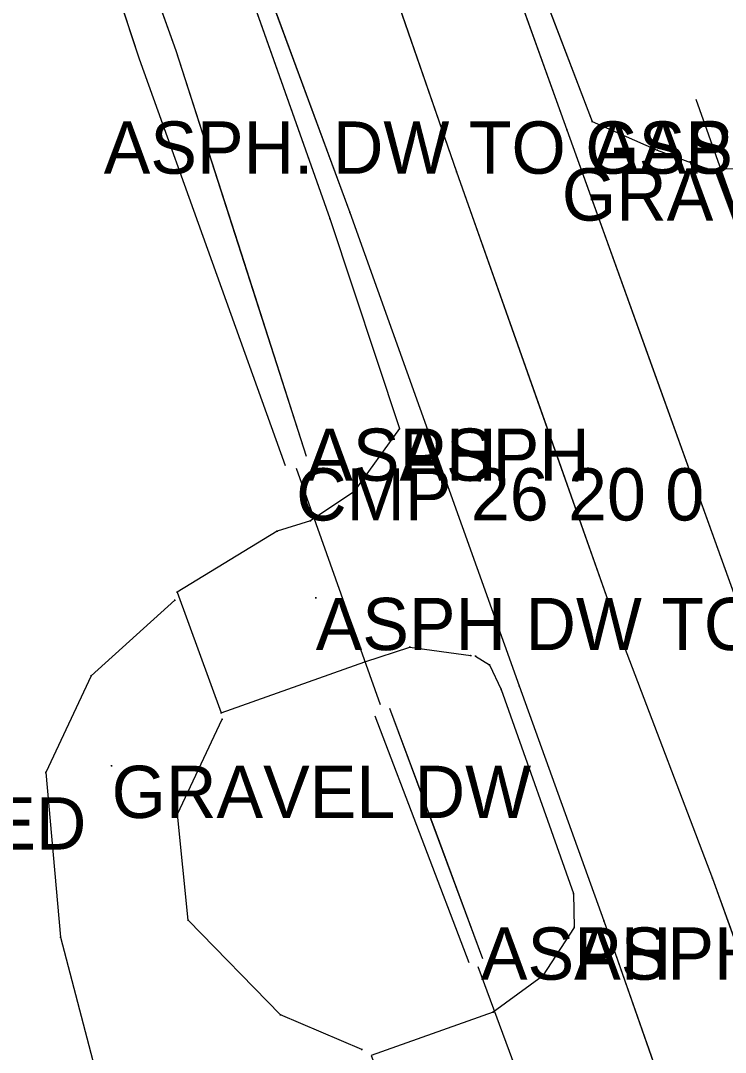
# Model space of a CAD drawing. Extents: x 1050807 to 1053552, y 395828 to 398415.
# Drawn here: x 1052568.2 to 1052635.6, y 396242.6 to 396341.3 of the extents above; entities that cross this region are included whole.
import ezdxf

# ---------------------------------------------------------------- set-up
doc = ezdxf.new("R2010")
doc.units = 0
for name, color, linetype in [('S_BUILDING_ANNOT', 7, 'Continuous'), ('S_DITCHLINE', 7, 'Continuous'), ('S_DRIVEWAY', 7, 'Continuous'), ('S_DRIVEWAY_ANNOT', 7, 'Continuous'), ('S_EDGE_PAVEMENT', 7, 'Continuous'), ('S_MSC_PT_SYM', 7, 'Continuous'), ('S_PAVEMENT_CROWN', 7, 'Continuous'), ('S_RDW_PT_SYM', 7, 'Continuous'), ('S_SHOULDER', 7, 'Continuous'), ('S_SHOULDER_ANNOT', 7, 'Continuous'), ('S_SIDE_DRAIN', 7, 'Continuous'), ('S_SIDE_DRAIN_ANNOT', 7, 'Continuous'), ('S_SURVEY_TEXT_ANNOT', 7, 'Continuous')]:
    doc.layers.add(name, color=color, linetype=linetype)

msp = doc.modelspace()

# ---------------------------------------------------------------- linework, layer by layer
at = {"layer": 'S_DITCHLINE'}
for p, q in [((1052563.191, 396393.977), (1052583.044, 396338.478)), ((1052561.346, 396392.877), (1052579.55, 396337.672)), ((1052583.044, 396338.478), (1052595.516, 396299.665)), ((1052579.55, 396337.672), (1052593.507, 396298.756)), ((1052602.092, 396274.814), (1052611.058, 396251.226)), ((1052603.491, 396275.547), (1052612.378, 396251.614))]:
    msp.add_line(p, q, dxfattribs=at)
for points in [[(1052541.957, 396445.771), (1052547.266, 396432.822), (1052552.574, 396419.874), (1052557.883, 396406.925), (1052563.191, 396393.977), (1052568.155, 396380.102), (1052573.118, 396366.227), (1052578.081, 396352.353), (1052583.044, 396338.478), (1052589.28, 396319.072), (1052595.516, 396299.665)], [(1052536.891, 396443.566), (1052543.005, 396430.894), (1052549.118, 396418.221), (1052555.232, 396405.549), (1052561.346, 396392.877), (1052565.897, 396379.076), (1052570.448, 396365.274), (1052574.999, 396351.473), (1052579.55, 396337.672), (1052586.528, 396318.214), (1052593.507, 396298.756)], [(1052602.092, 396274.814), (1052606.575, 396263.02), (1052611.058, 396251.226)], [(1052603.491, 396275.547), (1052607.934, 396263.58), (1052612.378, 396251.614)]]:
    msp.add_lwpolyline(points, dxfattribs=at)
at = {"layer": 'S_DRIVEWAY'}
for p, q in [((1052622.857, 396331.689), (1052629.097, 396328.944)), ((1052629.097, 396328.944), (1052633.836, 396327.174)), ((1052633.806, 396327.202), (1052655.11, 396326.952)), ((1052604.434, 396302.307), (1052600.061, 396296.258)), ((1052600.061, 396296.258), (1052595.917, 396293.493)), ((1052595.917, 396293.493), (1052592.732, 396292.491)), ((1052592.732, 396292.491), (1052583.161, 396286.642)), ((1052583.161, 396286.642), (1052587.388, 396275.096)), ((1052582.946, 396285.876), (1052574.934, 396278.66)), ((1052601.14, 396279.974), (1052605.445, 396281.406)), ((1052605.445, 396281.406), (1052611.279, 396280.587)), ((1052587.388, 396275.096), (1052601.14, 396279.974)), ((1052574.934, 396278.66), (1052570.597, 396269.388)), ((1052583.197, 396265.401), (1052587.487, 396274.5)), ((1052570.597, 396269.388), (1052572.024, 396253.632)), ((1052584.211, 396255.259), (1052583.197, 396265.401)), ((1052593.051, 396246.228), (1052584.211, 396255.259)), ((1052621.144, 396254.577), (1052618.117, 396249.902)), ((1052572.024, 396253.632), (1052575.274, 396241.216)), ((1052618.117, 396249.902), (1052613.385, 396246.473)), ((1052600.824, 396242.901), (1052593.051, 396246.228)), ((1052613.385, 396246.473), (1052601.718, 396242.339))]:
    msp.add_line(p, q, dxfattribs=at)
for points in [[(1052633.806, 396327.202), (1052655.11, 396326.952), (1052672.463, 396328.566), (1052689.815, 396330.179), (1052703.095, 396334.339), (1052716.376, 396338.498)], [(1052622.857, 396331.689), (1052629.097, 396328.944), (1052633.836, 396327.174)], [(1052604.434, 396302.307), (1052600.061, 396296.258), (1052595.917, 396293.493), (1052592.732, 396292.491), (1052583.161, 396286.642), (1052587.388, 396275.096), (1052601.14, 396279.974), (1052605.445, 396281.406), (1052611.279, 396280.587)], [(1052582.946, 396285.876), (1052574.934, 396278.66), (1052570.597, 396269.388), (1052572.024, 396253.632), (1052575.274, 396241.216), (1052579.85, 396231.29), (1052592.357, 396230.878), (1052604.218, 396232.057)], [(1052600.824, 396242.901), (1052593.051, 396246.228), (1052584.211, 396255.259), (1052583.197, 396265.401), (1052587.487, 396274.5)], [(1052621.144, 396254.577), (1052618.117, 396249.902), (1052613.385, 396246.473), (1052601.718, 396242.339), (1052606.278, 396230.472), (1052618.939, 396232.392), (1052625.998, 396231.881), (1052629.118, 396231.284)]]:
    msp.add_lwpolyline(points, dxfattribs=at)
at = {"layer": 'S_EDGE_PAVEMENT'}
for p, q in [((1052612.688, 396352.473), (1052620.452, 396330.901)), ((1052591.403, 396345.434), (1052599.696, 396322.98)), ((1052620.452, 396330.901), (1052636.983, 396284.917)), ((1052599.696, 396322.98), (1052615.89, 396277.68)), ((1052615.89, 396277.68), (1052623.975, 396255.211)), ((1052623.975, 396255.211), (1052634.417, 396225.496))]:
    msp.add_line(p, q, dxfattribs=at)
for points in [[(1052574.206, 396459.412), (1052580.36, 396442.372), (1052586.514, 396425.332), (1052593.054, 396407.062), (1052599.594, 396388.791), (1052606.141, 396370.632), (1052612.688, 396352.473), (1052620.452, 396330.901), (1052628.718, 396307.909), (1052636.983, 396284.917), (1052644.723, 396263.019), (1052649.92, 396248.391), (1052655.116, 396233.764)], [(1052553.664, 396451.671), (1052559.67, 396434.814), (1052565.676, 396417.956), (1052572.359, 396399.355), (1052579.042, 396380.754), (1052585.222, 396363.094), (1052591.403, 396345.434), (1052599.696, 396322.98), (1052607.793, 396300.33), (1052615.89, 396277.68), (1052623.975, 396255.211), (1052629.196, 396240.354)]]:
    msp.add_lwpolyline(points, dxfattribs=at)
at = {"layer": 'S_MSC_PT_SYM'}
for points in [[(1052596.423, 396286.11), (1052596.423, 396286.16), (1052596.423, 396286.11), (1052596.373, 396286.11), (1052596.423, 396286.11), (1052596.423, 396286.06), (1052596.423, 396286.11), (1052596.473, 396286.11)], [(1052576.907, 396270.047), (1052576.907, 396270.097), (1052576.907, 396270.047), (1052576.857, 396270.047), (1052576.907, 396270.047), (1052576.907, 396269.997), (1052576.907, 396270.047), (1052576.957, 396270.047)]]:
    msp.add_lwpolyline(points, dxfattribs=at)
at = {"layer": 'S_PAVEMENT_CROWN'}
for p, q in [((1052602.254, 396348.959), (1052609.906, 396326.87)), ((1052609.906, 396326.87), (1052625.942, 396281.452)), ((1052625.942, 396281.452), (1052634.394, 396259.265)), ((1052634.394, 396259.265), (1052644.906, 396230.007))]:
    msp.add_line(p, q, dxfattribs=at)
msp.add_lwpolyline([(1052563.845, 396455.267), (1052570.025, 396438.384), (1052576.205, 396421.501), (1052582.809, 396403.173), (1052589.412, 396384.846), (1052595.833, 396366.903), (1052602.254, 396348.959), (1052609.906, 396326.87), (1052617.924, 396304.161), (1052625.942, 396281.452), (1052634.394, 396259.265), (1052639.65, 396244.636), (1052644.906, 396230.007)], dxfattribs=at)
at = {"layer": 'S_RDW_PT_SYM'}
for points in [[(1052622.857, 396331.689), (1052622.857, 396331.739), (1052622.857, 396331.689), (1052622.807, 396331.689), (1052622.857, 396331.689), (1052622.857, 396331.639), (1052622.857, 396331.689), (1052622.907, 396331.689)], [(1052622.857, 396331.689), (1052622.857, 396331.739), (1052622.857, 396331.689), (1052622.807, 396331.689), (1052622.857, 396331.689), (1052622.857, 396331.639), (1052622.857, 396331.689), (1052622.907, 396331.689)], [(1052620.452, 396330.901), (1052620.452, 396330.951), (1052620.452, 396330.901), (1052620.402, 396330.901), (1052620.452, 396330.901), (1052620.452, 396330.851), (1052620.452, 396330.901), (1052620.502, 396330.901)], [(1052629.097, 396328.944), (1052629.097, 396328.994), (1052629.097, 396328.944), (1052629.047, 396328.944), (1052629.097, 396328.944), (1052629.097, 396328.894), (1052629.097, 396328.944), (1052629.147, 396328.944)], [(1052633.806, 396327.202), (1052633.806, 396327.252), (1052633.806, 396327.202), (1052633.756, 396327.202), (1052633.806, 396327.202), (1052633.806, 396327.152), (1052633.806, 396327.202), (1052633.856, 396327.202)], [(1052633.836, 396327.174), (1052633.836, 396327.224), (1052633.836, 396327.174), (1052633.786, 396327.174), (1052633.836, 396327.174), (1052633.836, 396327.124), (1052633.836, 396327.174), (1052633.886, 396327.174)], [(1052609.906, 396326.87), (1052609.906, 396326.92), (1052609.906, 396326.87), (1052609.856, 396326.87), (1052609.906, 396326.87), (1052609.906, 396326.82), (1052609.906, 396326.87), (1052609.956, 396326.87)], [(1052597.765, 396322.391), (1052597.765, 396322.441), (1052597.765, 396322.391), (1052597.715, 396322.391), (1052597.765, 396322.391), (1052597.765, 396322.341), (1052597.765, 396322.391), (1052597.815, 396322.391)], [(1052599.696, 396322.98), (1052599.696, 396323.03), (1052599.696, 396322.98), (1052599.646, 396322.98), (1052599.696, 396322.98), (1052599.696, 396322.93), (1052599.696, 396322.98), (1052599.746, 396322.98)], [(1052604.434, 396302.307), (1052604.434, 396302.357), (1052604.434, 396302.307), (1052604.384, 396302.307), (1052604.434, 396302.307), (1052604.434, 396302.257), (1052604.434, 396302.307), (1052604.484, 396302.307)], [(1052604.434, 396302.307), (1052604.434, 396302.357), (1052604.434, 396302.307), (1052604.384, 396302.307), (1052604.434, 396302.307), (1052604.434, 396302.257), (1052604.434, 396302.307), (1052604.484, 396302.307)], [(1052600.061, 396296.258), (1052600.061, 396296.308), (1052600.061, 396296.258), (1052600.011, 396296.258), (1052600.061, 396296.258), (1052600.061, 396296.208), (1052600.061, 396296.258), (1052600.111, 396296.258)], [(1052595.917, 396293.493), (1052595.917, 396293.543), (1052595.917, 396293.493), (1052595.867, 396293.493), (1052595.917, 396293.493), (1052595.917, 396293.443), (1052595.917, 396293.493), (1052595.967, 396293.493)], [(1052592.732, 396292.491), (1052592.732, 396292.541), (1052592.732, 396292.491), (1052592.682, 396292.491), (1052592.732, 396292.491), (1052592.732, 396292.441), (1052592.732, 396292.491), (1052592.782, 396292.491)], [(1052583.161, 396286.642), (1052583.161, 396286.692), (1052583.161, 396286.642), (1052583.111, 396286.642), (1052583.161, 396286.642), (1052583.161, 396286.592), (1052583.161, 396286.642), (1052583.211, 396286.642)], [(1052582.946, 396285.876), (1052582.946, 396285.926), (1052582.946, 396285.876), (1052582.896, 396285.876), (1052582.946, 396285.876), (1052582.946, 396285.826), (1052582.946, 396285.876), (1052582.996, 396285.876)], [(1052605.445, 396281.406), (1052605.445, 396281.456), (1052605.445, 396281.406), (1052605.395, 396281.406), (1052605.445, 396281.406), (1052605.445, 396281.356), (1052605.445, 396281.406), (1052605.495, 396281.406)], [(1052625.942, 396281.452), (1052625.942, 396281.502), (1052625.942, 396281.452), (1052625.892, 396281.452), (1052625.942, 396281.452), (1052625.942, 396281.402), (1052625.942, 396281.452), (1052625.992, 396281.452)], [(1052601.14, 396279.974), (1052601.14, 396280.024), (1052601.14, 396279.974), (1052601.09, 396279.974), (1052601.14, 396279.974), (1052601.14, 396279.924), (1052601.14, 396279.974), (1052601.19, 396279.974)], [(1052611.279, 396280.587), (1052611.279, 396280.637), (1052611.279, 396280.587), (1052611.229, 396280.587), (1052611.279, 396280.587), (1052611.279, 396280.537), (1052611.279, 396280.587), (1052611.329, 396280.587)], [(1052611.724, 396280.535), (1052611.724, 396280.585), (1052611.724, 396280.535), (1052611.674, 396280.535), (1052611.724, 396280.535), (1052611.724, 396280.485), (1052611.724, 396280.535), (1052611.774, 396280.535)], [(1052613.049, 396279.714), (1052613.049, 396279.764), (1052613.049, 396279.714), (1052612.999, 396279.714), (1052613.049, 396279.714), (1052613.049, 396279.664), (1052613.049, 396279.714), (1052613.099, 396279.714)], [(1052574.934, 396278.66), (1052574.934, 396278.71), (1052574.934, 396278.66), (1052574.884, 396278.66), (1052574.934, 396278.66), (1052574.934, 396278.61), (1052574.934, 396278.66), (1052574.984, 396278.66)], [(1052615.89, 396277.68), (1052615.89, 396277.73), (1052615.89, 396277.68), (1052615.84, 396277.68), (1052615.89, 396277.68), (1052615.89, 396277.63), (1052615.89, 396277.68), (1052615.94, 396277.68)], [(1052614.168, 396277.339), (1052614.168, 396277.389), (1052614.168, 396277.339), (1052614.118, 396277.339), (1052614.168, 396277.339), (1052614.168, 396277.289), (1052614.168, 396277.339), (1052614.218, 396277.339)], [(1052587.388, 396275.096), (1052587.388, 396275.146), (1052587.388, 396275.096), (1052587.338, 396275.096), (1052587.388, 396275.096), (1052587.388, 396275.046), (1052587.388, 396275.096), (1052587.438, 396275.096)], [(1052587.487, 396274.5), (1052587.487, 396274.55), (1052587.487, 396274.5), (1052587.437, 396274.5), (1052587.487, 396274.5), (1052587.487, 396274.45), (1052587.487, 396274.5), (1052587.537, 396274.5)], [(1052570.597, 396269.388), (1052570.597, 396269.438), (1052570.597, 396269.388), (1052570.547, 396269.388), (1052570.597, 396269.388), (1052570.597, 396269.338), (1052570.597, 396269.388), (1052570.647, 396269.388)], [(1052583.197, 396265.401), (1052583.197, 396265.451), (1052583.197, 396265.401), (1052583.147, 396265.401), (1052583.197, 396265.401), (1052583.197, 396265.351), (1052583.197, 396265.401), (1052583.247, 396265.401)], [(1052634.394, 396259.265), (1052634.394, 396259.315), (1052634.394, 396259.265), (1052634.344, 396259.265), (1052634.394, 396259.265), (1052634.394, 396259.215), (1052634.394, 396259.265), (1052634.444, 396259.265)], [(1052621.083, 396257.81), (1052621.083, 396257.86), (1052621.083, 396257.81), (1052621.033, 396257.81), (1052621.083, 396257.81), (1052621.083, 396257.76), (1052621.083, 396257.81), (1052621.133, 396257.81)], [(1052584.211, 396255.259), (1052584.211, 396255.309), (1052584.211, 396255.259), (1052584.161, 396255.259), (1052584.211, 396255.259), (1052584.211, 396255.209), (1052584.211, 396255.259), (1052584.261, 396255.259)], [(1052623.975, 396255.211), (1052623.975, 396255.261), (1052623.975, 396255.211), (1052623.925, 396255.211), (1052623.975, 396255.211), (1052623.975, 396255.161), (1052623.975, 396255.211), (1052624.025, 396255.211)], [(1052621.144, 396254.577), (1052621.144, 396254.627), (1052621.144, 396254.577), (1052621.094, 396254.577), (1052621.144, 396254.577), (1052621.144, 396254.527), (1052621.144, 396254.577), (1052621.194, 396254.577)], [(1052621.144, 396254.577), (1052621.144, 396254.627), (1052621.144, 396254.577), (1052621.094, 396254.577), (1052621.144, 396254.577), (1052621.144, 396254.527), (1052621.144, 396254.577), (1052621.194, 396254.577)], [(1052572.024, 396253.632), (1052572.024, 396253.682), (1052572.024, 396253.632), (1052571.974, 396253.632), (1052572.024, 396253.632), (1052572.024, 396253.582), (1052572.024, 396253.632), (1052572.074, 396253.632)], [(1052618.117, 396249.902), (1052618.117, 396249.952), (1052618.117, 396249.902), (1052618.067, 396249.902), (1052618.117, 396249.902), (1052618.117, 396249.852), (1052618.117, 396249.902), (1052618.167, 396249.902)], [(1052593.051, 396246.228), (1052593.051, 396246.278), (1052593.051, 396246.228), (1052593.001, 396246.228), (1052593.051, 396246.228), (1052593.051, 396246.178), (1052593.051, 396246.228), (1052593.101, 396246.228)], [(1052613.385, 396246.473), (1052613.385, 396246.523), (1052613.385, 396246.473), (1052613.335, 396246.473), (1052613.385, 396246.473), (1052613.385, 396246.423), (1052613.385, 396246.473), (1052613.435, 396246.473)], [(1052600.824, 396242.901), (1052600.824, 396242.951), (1052600.824, 396242.901), (1052600.774, 396242.901), (1052600.824, 396242.901), (1052600.824, 396242.851), (1052600.824, 396242.901), (1052600.874, 396242.901)]]:
    msp.add_lwpolyline(points, dxfattribs=at)
at = {"layer": 'S_SHOULDER'}
for p, q in [((1052614.723, 396353.06), (1052622.857, 396331.689)), ((1052589.854, 396344.752), (1052597.765, 396322.391)), ((1052597.765, 396322.391), (1052604.434, 396302.307)), ((1052611.724, 396280.535), (1052613.049, 396279.714)), ((1052613.049, 396279.714), (1052614.168, 396277.339)), ((1052614.168, 396277.339), (1052621.083, 396257.81)), ((1052621.083, 396257.81), (1052621.144, 396254.577))]:
    msp.add_line(p, q, dxfattribs=at)
for points in [[(1052576.272, 396459.797), (1052582.409, 396442.868), (1052588.546, 396425.939), (1052595.126, 396407.618), (1052601.705, 396389.298), (1052608.214, 396371.179), (1052614.723, 396353.06), (1052622.857, 396331.689)], [(1052551.322, 396450.929), (1052557.609, 396434.074), (1052563.896, 396417.22), (1052570.637, 396398.623), (1052577.379, 396380.027), (1052583.616, 396362.389), (1052589.854, 396344.752), (1052597.765, 396322.391), (1052604.434, 396302.307)], [(1052611.724, 396280.535), (1052613.049, 396279.714), (1052614.168, 396277.339), (1052621.083, 396257.81), (1052621.144, 396254.577)]]:
    msp.add_lwpolyline(points, dxfattribs=at)
at = {"layer": 'S_SIDE_DRAIN'}
for p, q in [((1052651.396, 396281.312), (1052632.813, 396333.803)), ((1052594.554, 396298.51), (1052602.601, 396275.909)), ((1052620.316, 396228.217), (1052611.955, 396250.801))]:
    msp.add_line(p, q, dxfattribs=at)

# ---------------------------------------------------------------- texts
at = {"layer": 'S_BUILDING_ANNOT'}
msp.add_text('1 STORY WOOD SHED', height=5, dxfattribs=at).set_placement((1052502.045, 396262.029))
at = {"layer": 'S_DRIVEWAY_ANNOT'}
for s, p in [('ASPH. DW TO GAS WELL', (1052576.148, 396326.689)), ('GRAVEL', (1052619.969, 396322.202)), ('ASPH', (1052595.518, 396297.307)), ('ASPH', (1052612.227, 396249.577))]:
    msp.add_text(s, height=5, dxfattribs=at).set_placement(p)
at = {"layer": 'S_SHOULDER_ANNOT'}
for s, p in [('ASPH. DW TO GAS WELL', (1052622.857, 396326.689)), ('ASPH', (1052604.434, 396297.307)), ('ASPH', (1052621.144, 396249.577))]:
    msp.add_text(s, height=5, dxfattribs=at).set_placement(p)
at = {"layer": 'S_SIDE_DRAIN_ANNOT'}
msp.add_text('CMP 26 20 0', height=5, dxfattribs=at).set_placement((1052594.554, 396293.51))
at = {"layer": 'S_SURVEY_TEXT_ANNOT'}
for s, p in [('ASPH DW TO ABANDONED 1-ST/WOOD ', (1052596.423, 396281.11)), ('GRAVEL DW', (1052576.907, 396265.047))]:
    msp.add_text(s, height=5, dxfattribs=at).set_placement(p)

doc.saveas('drawing.dxf')
